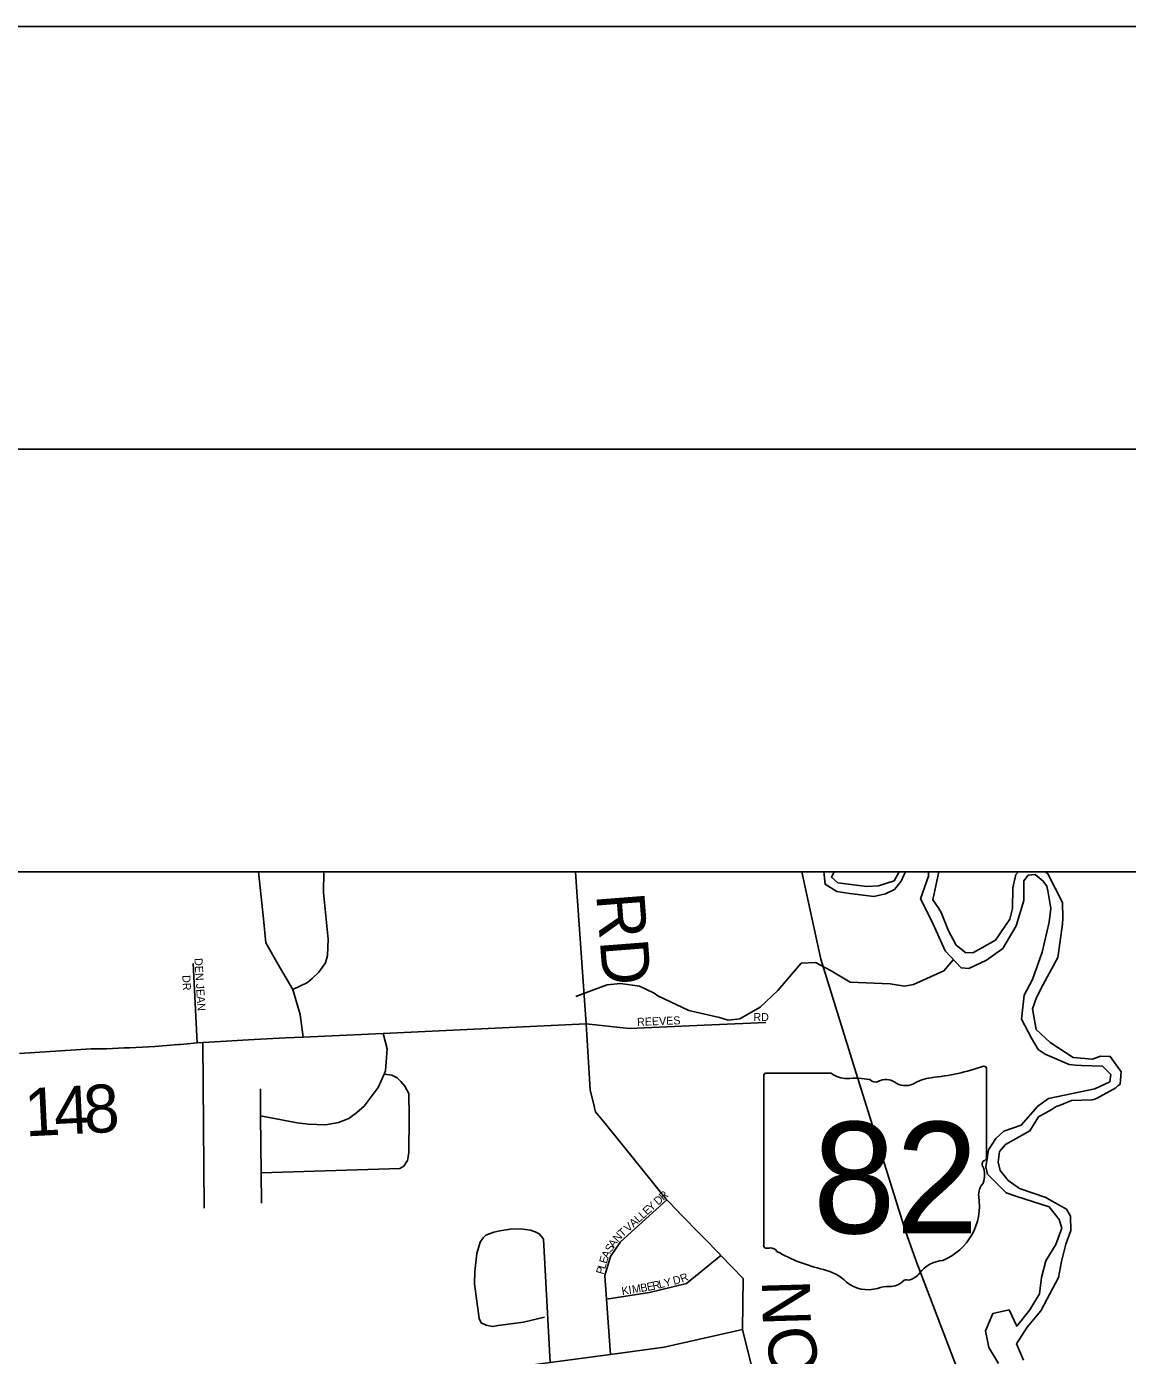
# Model space of a CAD drawing. Extents: x -37878.7 to -37844.7, y -19791.4 to -19769.4.
# Drawn here: x -37873.927 to -37872.624, y -19770.958 to -19769.385 of the extents above; entities that cross this region are included whole.
import ezdxf

# ---------------------------------------------------------------- set-up
doc = ezdxf.new("R2010")
doc.units = 0
for name, color, linetype in [('Default', 7, 'Continuous'), ('GM_X_City_Street', 7, 'Continuous'), ('GM_X_County_Road', 7, 'Continuous'), ('GM_X_County_Road_Text', 7, 'Continuous'), ('GM_X_Major_River', 7, 'Continuous'), ('GM_X_Minor_River', 7, 'Continuous'), ('GM_X_State_Route', 7, 'Continuous'), ('GM_X_State_Shield', 7, 'Continuous'), ('GM_X_Township_Subdivision', 7, 'Continuous'), ('GM_X_Township_Subdivision_Text', 7, 'Continuous'), ('SH_Border', 7, 'Continuous'), ('SH_Cut_Line', 7, 'Continuous'), ('SH_Data', 7, 'Continuous')]:
    doc.layers.add(name, color=color, linetype=linetype)

msp = doc.modelspace()

# ---------------------------------------------------------------- linework, layer by layer
at = {"layer": 'GM_X_City_Street'}
for points in [[(-37873.5996, -19770.5812), (-37873.603, -19770.5544), (-37873.6119, -19770.5247), (-37873.6277, -19770.4981), (-37873.6436, -19770.4694), (-37873.6463, -19770.441), (-37873.6525, -19770.3854)], [(-37873.6119, -19770.5247), (-37873.5945, -19770.5166), (-37873.5887, -19770.5119), (-37873.581, -19770.5041), (-37873.5732, -19770.4932), (-37873.5708, -19770.4845), (-37873.5698, -19770.4654), (-37873.5755, -19770.4102), (-37873.5752, -19770.3854)], [(-37873.6204, -19770.5821), (-37873.6203, -19770.5821), (-37873.5996, -19770.5812), (-37873.5047, -19770.5767), (-37873.2645, -19770.5654)], [(-37873.7167, -19770.7837), (-37873.7181, -19770.5875)], [(-37873.65, -19770.6744), (-37873.6066, -19770.6827), (-37873.5934, -19770.6841), (-37873.5731, -19770.6848), (-37873.5576, -19770.682), (-37873.5453, -19770.6776), (-37873.5358, -19770.6704), (-37873.5275, -19770.663), (-37873.5107, -19770.6409), (-37873.5038, -19770.6249), (-37873.5022, -19770.621), (-37873.4999, -19770.5951), (-37873.5047, -19770.5767)], [(-37873.6494, -19770.7416), (-37873.4853, -19770.7366), (-37873.4804, -19770.734), (-37873.4762, -19770.727), (-37873.4744, -19770.7181), (-37873.4741, -19770.6756), (-37873.4745, -19770.6479), (-37873.479, -19770.6392), (-37873.484, -19770.6337), (-37873.4881, -19770.6294), (-37873.4944, -19770.6261), (-37873.5038, -19770.6249)], [(-37873.649, -19770.7776), (-37873.6494, -19770.7416), (-37873.65, -19770.6744), (-37873.6499, -19770.6424)], [(-37873.2442, -19770.681), (-37873.2535, -19770.6696), (-37873.2547, -19770.6648), (-37873.2548, -19770.6645)], [(-37873.1752, -19770.7664), (-37873.1876, -19770.7509), (-37873.1877, -19770.7508)], [(-37873.3072, -19770.9662), (-37873.315, -19770.8202), (-37873.3177, -19770.8167), (-37873.3203, -19770.8141), (-37873.3248, -19770.8114), (-37873.3303, -19770.8096), (-37873.3422, -19770.8079), (-37873.3547, -19770.8083), (-37873.3667, -19770.8104), (-37873.374, -19770.812), (-37873.3833, -19770.8156), (-37873.3866, -19770.8187), (-37873.39, -19770.8238), (-37873.3939, -19770.837), (-37873.3965, -19770.8584), (-37873.3966, -19770.8729), (-37873.3913, -19770.9142), (-37873.3887, -19770.9194), (-37873.3831, -19770.9219), (-37873.3756, -19770.9237), (-37873.3689, -19770.9225), (-37873.3388, -19770.9184), (-37873.314, -19770.9127)], [(-37874.8938, -19771.2024), (-37874.8625, -19771.1977), (-37874.7737, -19771.1822), (-37874.6932, -19771.1668), (-37874.5704, -19771.1472), (-37874.3994, -19771.12), (-37874.222, -19771.0918), (-37874.1614, -19771.0842), (-37874.0992, -19771.0764), (-37874.0336, -19771.0681), (-37873.968, -19771.0599), (-37873.8957, -19771.0508), (-37873.5871, -19771.008), (-37873.5852, -19771.0077), (-37873.3651, -19770.974), (-37873.3072, -19770.9662), (-37873.2357, -19770.9566), (-37873.1722, -19770.948), (-37873.0796, -19770.9272)]]:
    msp.add_lwpolyline(points, dxfattribs=at)
at = {"layer": 'GM_X_County_Road'}
for points in [[(-37873.2645, -19770.5654), (-37873.2761, -19770.4035), (-37873.2771, -19770.3854)], [(-37873.2548, -19770.6645), (-37873.26, -19770.6436), (-37873.2645, -19770.5654)], [(-37873.8051, -19770.5937), (-37873.775, -19770.5924), (-37873.7476, -19770.59), (-37873.745, -19770.5897)], [(-37873.745, -19770.5897), (-37873.7446, -19770.5897), (-37873.725, -19770.5879), (-37873.7181, -19770.5875), (-37873.7041, -19770.5867)], [(-37873.7041, -19770.5867), (-37873.7039, -19770.5866), (-37873.6576, -19770.5839), (-37873.6204, -19770.5821)], [(-37873.9353, -19770.6004), (-37873.8505, -19770.5952), (-37873.8453, -19770.5952), (-37873.8452, -19770.5952)], [(-37873.8452, -19770.5952), (-37873.8317, -19770.5952), (-37873.8251, -19770.5948)], [(-37873.8251, -19770.5948), (-37873.8249, -19770.5948), (-37873.8113, -19770.5939), (-37873.8053, -19770.5937), (-37873.8051, -19770.5937)], [(-37873.1877, -19770.7508), (-37873.2303, -19770.6978), (-37873.2441, -19770.681), (-37873.2442, -19770.681)], [(-37873.1549, -19770.7884), (-37873.1693, -19770.7736), (-37873.1701, -19770.7728), (-37873.1751, -19770.7666), (-37873.1752, -19770.7664)], [(-37873.1271, -19770.817), (-37873.1548, -19770.7886), (-37873.1549, -19770.7884)], [(-37873.1062, -19770.8385), (-37873.1269, -19770.8172), (-37873.1271, -19770.817)], [(-37873.0796, -19770.9272), (-37873.0789, -19770.8667), (-37873.1052, -19770.8396), (-37873.106, -19770.8387), (-37873.1062, -19770.8385)], [(-37873.0224, -19771.1487), (-37873.0224, -19771.1486), (-37873.0349, -19771.1067), (-37873.0684, -19770.9716), (-37873.0796, -19770.9272)]]:
    msp.add_lwpolyline(points, dxfattribs=at)
at = {"layer": 'GM_X_Major_River'}
for points in [[(-37872.8868, -19770.3854), (-37872.8888, -19770.3894), (-37872.8919, -19770.3967), (-37872.8997, -19770.4064), (-37872.9102, -19770.4115), (-37872.9241, -19770.4148), (-37872.9527, -19770.4111), (-37872.9681, -19770.4088), (-37872.9819, -19770.4003), (-37872.9835, -19770.3854)], [(-37872.9712, -19770.3854), (-37872.9744, -19770.3918), (-37872.9668, -19770.3985), (-37872.9323, -19770.4028), (-37872.9187, -19770.4022), (-37872.9002, -19770.3961), (-37872.8941, -19770.3854)], [(-37872.7017, -19770.8071), (-37872.7048, -19770.797), (-37872.7168, -19770.782), (-37872.7548, -19770.7698), (-37872.7677, -19770.7655), (-37872.7897, -19770.7435), (-37872.7917, -19770.7345), (-37872.7883, -19770.7147), (-37872.7798, -19770.7012), (-37872.7702, -19770.6923), (-37872.7499, -19770.6855), (-37872.7302, -19770.6628), (-37872.7175, -19770.6538), (-37872.6625, -19770.6422), (-37872.6449, -19770.6339), (-37872.6435, -19770.6255), (-37872.6535, -19770.6154), (-37872.6785, -19770.6149), (-37872.6854, -19770.6144), (-37872.6929, -19770.6135), (-37872.7215, -19770.6015), (-37872.7295, -19770.5956), (-37872.7377, -19770.5825), (-37872.7494, -19770.5599), (-37872.7462, -19770.5314), (-37872.7363, -19770.513), (-37872.7248, -19770.4805), (-37872.7167, -19770.4451), (-37872.7147, -19770.4288), (-37872.7177, -19770.4102), (-37872.7196, -19770.4024), (-37872.7236, -19770.3966), (-37872.7332, -19770.3889), (-37872.7373, -19770.3893), (-37872.7415, -19770.3894), (-37872.7467, -19770.3963), (-37872.7466, -19770.4195), (-37872.7559, -19770.4493), (-37872.7714, -19770.4761), (-37872.7908, -19770.4901), (-37872.8118, -19770.5), (-37872.8209, -19770.499), (-37872.8398, -19770.4789), (-37872.8555, -19770.4439), (-37872.8688, -19770.4176), (-37872.8595, -19770.3908), (-37872.8596, -19770.3854)], [(-37872.8471, -19770.3854), (-37872.8544, -19770.4188), (-37872.8471, -19770.4289), (-37872.8443, -19770.4338), (-37872.8357, -19770.4553), (-37872.8266, -19770.4722), (-37872.8151, -19770.4814)], [(-37872.8151, -19770.4814), (-37872.8064, -19770.4809), (-37872.7802, -19770.4664), (-37872.7633, -19770.4414), (-37872.7601, -19770.4288), (-37872.7598, -19770.4046), (-37872.7563, -19770.3889), (-37872.753, -19770.3854)], [(-37872.721, -19770.3854), (-37872.7181, -19770.3879), (-37872.7008, -19770.4217), (-37872.7006, -19770.4403), (-37872.7007, -19770.4475), (-37872.7065, -19770.487), (-37872.7237, -19770.5188), (-37872.7317, -19770.5342), (-37872.7364, -19770.5475), (-37872.7322, -19770.5721), (-37872.7153, -19770.5874), (-37872.6881, -19770.6051), (-37872.6654, -19770.6073), (-37872.656, -19770.6037), (-37872.6443, -19770.6039), (-37872.6315, -19770.6222), (-37872.6327, -19770.6367), (-37872.6354, -19770.6388), (-37872.6379, -19770.6413), (-37872.66, -19770.6535), (-37872.6638, -19770.6551), (-37872.6661, -19770.6555), (-37872.6902, -19770.656), (-37872.7045, -19770.6619), (-37872.7083, -19770.6631), (-37872.7143, -19770.667), (-37872.7292, -19770.6756), (-37872.7395, -19770.6921), (-37872.7684, -19770.7082), (-37872.7754, -19770.7163), (-37872.7771, -19770.7293), (-37872.7746, -19770.7391), (-37872.765, -19770.751), (-37872.7516, -19770.7603), (-37872.7207, -19770.7711), (-37872.7165, -19770.7733), (-37872.6963, -19770.7847), (-37872.6916, -19770.7929), (-37872.6909, -19770.81)], [(-37872.7017, -19770.8071), (-37872.7089, -19770.8266), (-37872.7206, -19770.8459), (-37872.7259, -19770.8657), (-37872.7282, -19770.8848), (-37872.7395, -19770.904), (-37872.755, -19770.9233), (-37872.7641, -19770.9038), (-37872.7834, -19770.9083), (-37872.792, -19770.9286), (-37872.7882, -19770.9483), (-37872.7765, -19770.9674)], [(-37872.6909, -19770.81), (-37872.6968, -19770.826), (-37872.7021, -19770.8466), (-37872.7058, -19770.8657), (-37872.7157, -19770.8849), (-37872.7266, -19770.9052), (-37872.7425, -19770.9245), (-37872.7553, -19770.9442), (-37872.747, -19770.9634)]]:
    msp.add_lwpolyline(points, dxfattribs=at)
at = {"layer": 'GM_X_Minor_River'}
msp.add_lwpolyline([(-37872.83, -19770.4893), (-37872.8412, -19770.5028), (-37872.8773, -19770.519), (-37872.8878, -19770.5207), (-37872.9049, -19770.518), (-37872.9522, -19770.5162), (-37872.9748, -19770.5026), (-37872.9931, -19770.4927), (-37873.0101, -19770.4938), (-37873.0379, -19770.5258), (-37873.0587, -19770.5459), (-37873.0827, -19770.5596), (-37873.0966, -19770.561), (-37873.1069, -19770.5578), (-37873.143, -19770.5497), (-37873.1796, -19770.5322), (-37873.1842, -19770.5292), (-37873.2014, -19770.5208), (-37873.2241, -19770.5178), (-37873.2396, -19770.5192), (-37873.2546, -19770.5248), (-37873.2768, -19770.5332)], dxfattribs=at)
at = {"layer": 'GM_X_State_Route'}
for points in [[(-37873.0095, -19770.3854), (-37872.987, -19770.4889), (-37872.9485, -19770.6123)], [(-37872.9485, -19770.6123), (-37872.9485, -19770.6125), (-37872.8866, -19770.8107), (-37872.8725, -19770.8507)], [(-37872.8725, -19770.8507), (-37872.8722, -19770.8513), (-37872.7691, -19771.121), (-37872.7253, -19771.2353), (-37872.7038, -19771.2924), (-37872.688, -19771.3374)]]:
    msp.add_lwpolyline(points, dxfattribs=at)
at = {"layer": 'GM_X_State_Shield'}
for p, q in [((-37872.7908, -19770.7236), (-37872.7908, -19770.6189)), ((-37873.0545, -19770.6273), (-37873.0545, -19770.8274)), ((-37872.9747, -19770.6239), (-37873.0519, -19770.6239)), ((-37872.7909, -19770.7236), (-37872.7908, -19770.7236))]:
    msp.add_line(p, q, dxfattribs=at)
for centre, radius, start, end in [((-37872.8848, -19770.351), 0.2796, 275.8445, 288.9065), ((-37872.7938, -19770.6185), 0.00294, 351.8621, 97.738), ((-37873.0515, -19770.6269), 0.00305, 98.1301, 188.1301), ((-37872.9563, -19770.6006), 0.0296, 231.6195, 271.1119), ((-37872.9465, -19770.7362), 0.1064, 80.4867, 94.9883), ((-37872.9223, -19770.6258), 0.00855, 219.7921, 297.1024), ((-37872.9098, -19770.649), 0.0178, 54.4667, 119.1411), ((-37872.8868, -19770.6172), 0.0214, 233.8562, 294.8282), ((-37872.8491, -19770.685), 0.0563, 97.3462, 120.7689), ((-37872.7915, -19770.7313), 0.00454, 107.944, 210.337), ((-37872.794, -19770.724), 0.00314, 289.6038, 7.7341), ((-37872.8204, -19770.7445), 0.0273, 340.033, 23.6496), ((-37872.7803, -19770.7674), 0.0198, 136.8065, 186.9296), ((-37872.8691, -19770.7807), 0.0699, 292.3089, 8.9858), ((-37873.0515, -19770.8279), 0.00308, 171.9584, 258.3066), ((-37873.051, -19770.8074), 0.0235, 267.339, 280.6039), ((-37873.0462, -19770.839), 0.00848, 29.7484, 93.2717), ((-37872.9391, -19770.6592), 0.2019, 240.4129, 257.1985), ((-37872.9993, -19770.9173), 0.0632, 47.1842, 75.836), ((-37872.8396, -19770.8836), 0.0383, 94.4031, 142.5768), ((-37872.931, -19770.84), 0.0401, 230.7004, 286.2918), ((-37872.9049, -19770.8549), 0.0214, 268.777, 315.5493), ((-37872.8856, -19770.8743), 0.00601, 65.7517, 132.6484), ((-37872.8881, -19770.8468), 0.0226, 282.8732, 323.2771), ((-37872.9078, -19770.9091), 0.0329, 85.6951, 111.2099)]:
    msp.add_arc(centre, radius, start, end, dxfattribs=at)
at = {"layer": 'GM_X_Township_Subdivision'}
for points in [[(-37873.725, -19770.5879), (-37873.7296, -19770.4942)], [(-37873.2645, -19770.5654), (-37873.2139, -19770.5708), (-37873.1159, -19770.5666), (-37873.1159, -19770.5666)], [(-37873.1159, -19770.5666), (-37873.0521, -19770.5638)], [(-37873.2357, -19770.9566), (-37873.2405, -19770.8914), (-37873.2426, -19770.8633), (-37873.2359, -19770.8406), (-37873.224, -19770.8235), (-37873.2027, -19770.804), (-37873.1693, -19770.7736)], [(-37873.1052, -19770.8396), (-37873.1458, -19770.8728), (-37873.1898, -19770.8833), (-37873.2405, -19770.8914)]]:
    msp.add_lwpolyline(points, dxfattribs=at)
at = {"layer": 'SH_Border'}
msp.add_lwpolyline([(-37876.6504, -19769.8854), (-37845.1504, -19769.8854), (-37845.1504, -19790.8854), (-37876.6504, -19790.8854)], close=True, dxfattribs=at)
at = {"layer": 'SH_Cut_Line'}
msp.add_lwpolyline([(-37878.6504, -19791.3854), (-37844.6504, -19791.3854), (-37844.6504, -19769.3854), (-37878.6504, -19769.3854)], close=True, dxfattribs=at)
at = {"layer": 'SH_Data'}
msp.add_line((-37876.1504, -19770.3854), (-37869.1504, -19770.3854), dxfattribs=at)

# ---------------------------------------------------------------- texts
at = {"layer": 'Default'}
for s in ['s', 'r']:
    msp.add_text(s, height=0.000189, dxfattribs=at).set_placement((-37872.9256, -19770.7407))
msp.add_text('82', height=0.000189, rotation=0, dxfattribs=at).set_placement((-37872.9733, -19770.7544))
at = {"layer": 'GM_X_County_Road_Text'}
for s, height, rotation, p in [('RD', 0.05682, 274.436, (-37873.2527, -19770.4122)), ('4', 0.0568, 2.8618, (-37873.8931, -19770.6969)), ('8', 0.0568, 3.217, (-37873.8578, -19770.6952)), ('1', 0.0568, 2.8298, (-37873.9281, -19770.6987)), ('N', 0.0568, 271.6103, (-37873.0568, -19770.869)), ('O', 0.0568, 281.7331, (-37873.0541, -19770.9299))]:
    msp.add_text(s, height=height, rotation=rotation, dxfattribs=at).set_placement(p)
at = {"layer": 'GM_X_State_Shield'}
msp.add_text('82', height=0.13184, dxfattribs=at).set_placement((-37872.9964, -19770.8133))
at = {"layer": 'GM_X_Township_Subdivision_Text'}
for s, rotation, p in [('DEN JEAN', 273.4696, (-37873.7282, -19770.4879)), ('DR', 273.0113, (-37873.7426, -19770.508)), ('REEVES', 2.2013, (-37873.2042, -19770.5679)), ('RD', 0, (-37873.0667, -19770.5621)), ('R', 41.8187, (-37873.1732, -19770.7751)), ('E', 41.8155, (-37873.1925, -19770.7923)), ('Y', 41.8227, (-37873.1875, -19770.7878)), ('D', 41.815, (-37873.1794, -19770.7806)), ('L', 41.8331, (-37873.2024, -19770.8012)), ('L', 41.8105, (-37873.1974, -19770.7967)), ('T', 42.1111, (-37873.2216, -19770.8184)), ('V', 41.815, (-37873.2148, -19770.8123)), ('A', 41.8227, (-37873.2086, -19770.8067)), ('S', 56.6737, (-37873.2352, -19770.8365)), ('A', 55.7098, (-37873.2316, -19770.831)), ('N', 47.2647, (-37873.2271, -19770.8244)), ('E', 73.2777, (-37873.2404, -19770.8498)), ('A', 64.7791, (-37873.2386, -19770.8438)), ('P', 73.289, (-37873.2442, -19770.8626)), ('L', 73.2777, (-37873.2423, -19770.8562)), ('M', 9.1405, (-37873.2096, -19770.8844)), ('B', 9.1347, (-37873.1997, -19770.8828)), ('E', 11.3593, (-37873.1919, -19770.8816)), ('R', 13.079, (-37873.1851, -19770.8802)), ('L', 13.7443, (-37873.1777, -19770.8785)), ('Y', 13.7409, (-37873.1712, -19770.8769)), ('D', 13.7339, (-37873.1607, -19770.8743)), ('R', 22.3741, (-37873.1511, -19770.8719)), ('K', 9.1317, (-37873.2219, -19770.8864)), ('I', 9.1382, (-37873.2137, -19770.8851))]:
    msp.add_text(s, height=0.00947, rotation=rotation, dxfattribs=at).set_placement(p)

doc.saveas('drawing.dxf')
